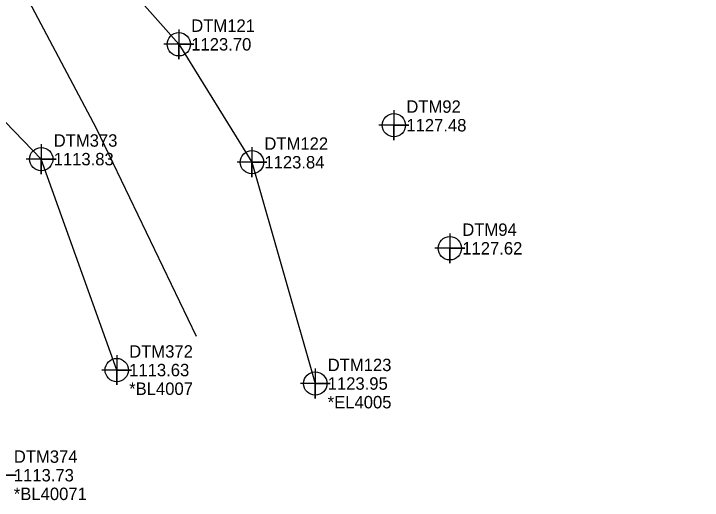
# Model space of a CAD drawing. Extents: x 1286409 to 1286829, y 857931 to 858308.
# Drawn here: x 1286649.1 to 1286787.6, y 858032.1 to 858130 of the extents above; entities that cross this region are included whole.
import ezdxf

# ---------------------------------------------------------------- set-up
doc = ezdxf.new("R2010")
doc.units = 0
for name, color, linetype in [('Exist DTM Breakline', 7, 'Continuous'), ('Exist DTM Breakline Cogo Comment', 7, 'Continuous'), ('Exist DTM Breakline Cogo Elevation', 7, 'Continuous'), ('Exist DTM Breakline Cogo Number', 7, 'Continuous'), ('Exist DTM Breakline Cogo Point CELL', 7, 'Continuous'), ('Exist DTM Breakline Underwater', 7, 'Continuous'), ('Exist DTM Breakline Underwater Cogo Comment', 7, 'Continuous'), ('Exist DTM Breakline Underwater Cogo Elevation', 7, 'Continuous'), ('Exist DTM Breakline Underwater Cogo Number', 7, 'Continuous'), ('Exist DTM Breakline Underwater Cogo Point CELL', 7, 'Continuous'), ('Exist DTM Regular Point CELL', 7, 'Continuous'), ('Exist DTM Regular Point Cogo Elevation', 7, 'Continuous'), ('Exist DTM Regular Point Cogo Number', 7, 'Continuous'), ('Exist Hydro Stream or Body of Water', 7, 'Continuous')]:
    doc.layers.add(name, color=color, linetype=linetype)

msp = doc.modelspace()

# ---------------------------------------------------------------- linework, layer by layer
at = {"layer": 'Exist DTM Breakline'}
msp.add_lwpolyline([(1286787.57, 858150.977), (1286775.181, 858174.894), (1286765.217, 858193.137), (1286755.797, 858193.361), (1286718.64, 858178.527), (1286680.221, 858159.977), (1286675.641, 858160.401), (1286671.867, 858162.031), (1286662.339, 858153.405), (1286673.303, 858134.067), (1286682.298, 858123.811), (1286697.007, 858100.077), (1286709.742, 858055.54)], dxfattribs=at)
at = {"layer": 'Exist DTM Breakline Cogo Point CELL'}
for points in [[(1286682.298, 858126.811), (1286682.298, 858120.811), (1286682.298, 858123.811), (1286685.298, 858123.811), (1286679.298, 858123.811)], [(1286697.007, 858103.077), (1286697.007, 858097.077), (1286697.007, 858100.077), (1286700.007, 858100.077), (1286694.007, 858100.077)], [(1286709.742, 858058.54), (1286709.742, 858052.54), (1286709.742, 858055.54), (1286712.742, 858055.54), (1286706.742, 858055.54)]]:
    msp.add_lwpolyline(points, dxfattribs=at)
for centre in [(1286682.298, 858123.811), (1286697.007, 858100.077), (1286709.742, 858055.54)]:
    msp.add_circle(centre, 2.344, dxfattribs=at)
at = {"layer": 'Exist DTM Breakline Underwater'}
msp.add_lwpolyline([(1286669.815, 858058.251), (1286654.631, 858100.703), (1286613.243, 858143.649), (1286609.52, 858180.682), (1286592.241, 858242.731), (1286573.236, 858288.883)], dxfattribs=at)
at = {"layer": 'Exist DTM Breakline Underwater Cogo Point CELL'}
for points in [[(1286654.631, 858103.703), (1286654.631, 858097.703), (1286654.631, 858100.703), (1286657.631, 858100.703), (1286651.631, 858100.703)], [(1286669.815, 858061.251), (1286669.815, 858055.251), (1286669.815, 858058.251), (1286672.815, 858058.251), (1286666.815, 858058.251)], [(1286646.614, 858040.087), (1286646.614, 858034.087), (1286646.614, 858037.087), (1286649.614, 858037.087), (1286643.614, 858037.087)]]:
    msp.add_lwpolyline(points, dxfattribs=at)
for centre in [(1286654.631, 858100.703), (1286669.815, 858058.251)]:
    msp.add_circle(centre, 2.344, dxfattribs=at)
at = {"layer": 'Exist DTM Regular Point CELL'}
for points in [[(1286725.559, 858110.525), (1286725.559, 858104.525), (1286725.559, 858107.525), (1286728.559, 858107.525), (1286722.559, 858107.525)], [(1286736.807, 858085.756), (1286736.807, 858079.756), (1286736.807, 858082.756), (1286739.807, 858082.756), (1286733.807, 858082.756)]]:
    msp.add_lwpolyline(points, dxfattribs=at)
for centre in [(1286725.559, 858107.525), (1286736.807, 858082.756)]:
    msp.add_circle(centre, 2.344, dxfattribs=at)
at = {"layer": 'Exist Hydro Stream or Body of Water'}
msp.add_lwpolyline([(1286685.865, 858065.012), (1286665.776, 858106.892), (1286641.007, 858153.512), (1286624.223, 858201.931), (1286608.049, 858245.959), (1286588.044, 858292.077)], dxfattribs=at)

# ---------------------------------------------------------------- texts
at = {"layer": 'Exist DTM Breakline Cogo Comment'}
msp.add_text('*EL4005', height=2.5, dxfattribs=at).set_placement((1286712.242, 858050.54))
at = {"layer": 'Exist DTM Breakline Cogo Elevation'}
for s, p in [('1123.70', (1286684.798, 858122.561)), ('1123.84', (1286699.507, 858098.827)), ('1123.95', (1286712.242, 858054.29))]:
    msp.add_text(s, height=2.5, dxfattribs=at).set_placement(p)
at = {"layer": 'Exist DTM Breakline Cogo Number'}
for s, p in [('DTM121', (1286684.798, 858126.311)), ('DTM122', (1286699.507, 858102.577)), ('DTM123', (1286712.242, 858058.04))]:
    msp.add_text(s, height=2.5, dxfattribs=at).set_placement(p)
at = {"layer": 'Exist DTM Breakline Underwater Cogo Comment'}
for s, p in [('*BL4007', (1286672.315, 858053.251)), ('*BL40071', (1286649.114, 858032.087))]:
    msp.add_text(s, height=2.5, dxfattribs=at).set_placement(p)
at = {"layer": 'Exist DTM Breakline Underwater Cogo Elevation'}
for s, p in [('1113.83', (1286657.131, 858099.453)), ('1113.63', (1286672.315, 858057.001)), ('1113.73', (1286649.114, 858035.837))]:
    msp.add_text(s, height=2.5, dxfattribs=at).set_placement(p)
at = {"layer": 'Exist DTM Breakline Underwater Cogo Number'}
for s, p in [('DTM373', (1286657.131, 858103.203)), ('DTM372', (1286672.315, 858060.751)), ('DTM374', (1286649.114, 858039.587))]:
    msp.add_text(s, height=2.5, dxfattribs=at).set_placement(p)
at = {"layer": 'Exist DTM Regular Point Cogo Elevation'}
for s, p in [('1127.48', (1286728.059, 858106.275)), ('1127.62', (1286739.307, 858081.506))]:
    msp.add_text(s, height=2.5, dxfattribs=at).set_placement(p)
at = {"layer": 'Exist DTM Regular Point Cogo Number'}
for s, p in [('DTM92', (1286728.059, 858110.025)), ('DTM94', (1286739.307, 858085.256))]:
    msp.add_text(s, height=2.5, dxfattribs=at).set_placement(p)

doc.saveas('drawing.dxf')
